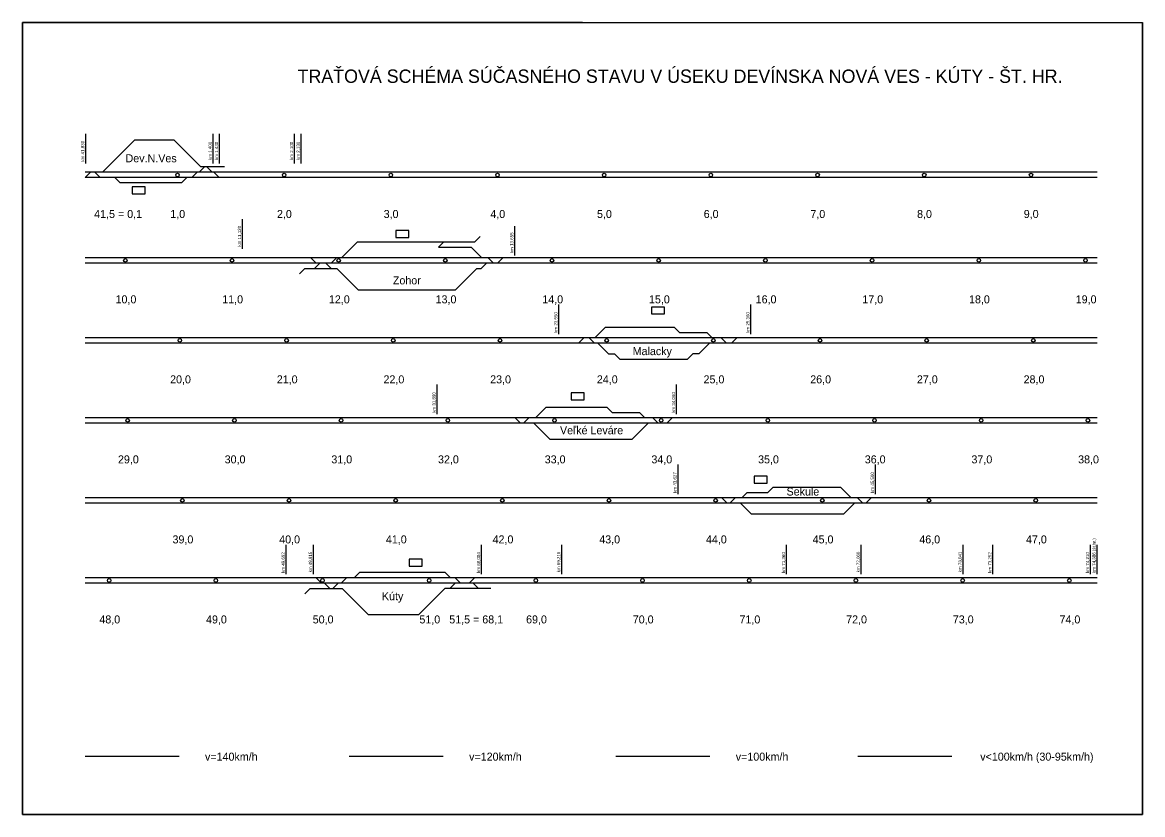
# Model space of a CAD drawing. Extents: x 44 to 1904, y 374 to 671.
# Drawn here: x 44.1 to 464.1, y 373.6 to 670.6 of the extents above; entities that cross this region are included whole.
import ezdxf

# ---------------------------------------------------------------- set-up
doc = ezdxf.new("R2010")
doc.units = 0
for name, color, linetype in [('2', 7, 'Continuous'), ('NAVRH', 7, 'Continuous'), ('Vrstva 1', 7, 'Continuous')]:
    doc.layers.add(name, color=color, linetype=linetype)

msp = doc.modelspace()

# ---------------------------------------------------------------- linework, layer by layer
at = {"layer": '2'}
for p, q in [((297.69, 546.39), (295.39, 546.39)), ((173.74, 448.65), (192.74, 448.65))]:
    msp.add_line(p, q, dxfattribs=at)
at = {"layer": 'NAVRH'}
for p, q in [((74.13, 614.39), (86.13, 626.39)), ((110.92, 616.39), (100.92, 626.39)), ((67.56, 612.39), (69.56, 614.39)), ((73.19, 612.39), (71.19, 614.39)), ((107.55, 612.39), (109.55, 614.39)), ((110.29, 614.39), (112.29, 616.39)), ((115.24, 614.39), (113.24, 616.39)), ((117.85, 612.39), (115.85, 614.39)), ((80.67, 610.39), (78.67, 612.39)), ((103.74, 610.39), (105.74, 612.39)), ((163.68, 582.39), (169.68, 588.39)), ((200.09, 586.39), (202.09, 588.39)), ((213.68, 588.39), (215.68, 590.39)), ((216.37, 582.39), (212.37, 586.39)), ((154.27, 580.39), (152.27, 582.39)), ((153.63, 578.39), (155.63, 580.39)), ((159.81, 578.39), (157.81, 580.39)), ((159.83, 580.39), (161.83, 582.39)), ((216.04, 578.39), (218.04, 580.39)), ((220.73, 580.39), (218.73, 582.39)), ((222.25, 580.39), (224.25, 582.39)), ((147.91, 576.39), (149.91, 578.39)), ((170.01, 570.39), (162.01, 578.39)), ((206.52, 570.39), (214.52, 578.39)), ((258.7, 552.39), (262.7, 556.39)), ((288.49, 556.39), (290.49, 554.39)), ((252.63, 550.39), (254.63, 552.39)), ((258.59, 550.39), (256.59, 552.39)), ((259.86, 550.39), (263.86, 546.39)), ((297.69, 546.39), (301.69, 550.39)), ((300.67, 554.39), (302.67, 552.39)), ((308.07, 550.39), (306.07, 552.39)), ((309.9, 550.39), (311.9, 552.39)), ((266.02, 546.39), (268.02, 544.39)), ((293.39, 544.39), (295.39, 546.39)), ((236.44, 522.39), (240.44, 526.39)), ((265.24, 524.39), (263.24, 526.39)), ((230.86, 520.39), (228.86, 522.39)), ((231.92, 520.39), (233.92, 522.39)), ((277.41, 522.39), (275.41, 524.39)), ((282.47, 520.39), (280.47, 522.39)), ((285.73, 520.39), (287.73, 522.39)), ((241.87, 514.39), (235.87, 520.39)), ((272.7, 514.39), (278.7, 520.39)), ((323.51, 494.39), (325.51, 496.39)), ((354.84, 492.39), (350.84, 496.39)), ((308.29, 490.39), (306.29, 492.39)), ((309.34, 490.39), (311.34, 492.39)), ((313.87, 492.39), (315.87, 494.39)), ((359.23, 490.39), (357.23, 492.39)), ((360.29, 490.39), (362.29, 492.39)), ((317.3, 486.39), (313.3, 490.39)), ((352.12, 486.39), (356.12, 490.39)), ((156.27, 460.39), (154.27, 462.39)), ((163.6, 460.39), (165.6, 462.39)), ((170.52, 464.39), (168.52, 462.39)), ((202.62, 464.39), (204.62, 462.39)), ((208.34, 460.39), (206.34, 462.39)), ((211.59, 460.39), (213.59, 462.39)), ((149.91, 456.39), (151.91, 458.39)), ((159.33, 458.39), (157.33, 460.39)), ((160.45, 458.39), (162.45, 460.39)), ((173.74, 448.65), (164.01, 458.39)), ((192.74, 448.65), (202.47, 458.39)), ((204.3, 458.39), (206.3, 460.39)), ((215.12, 458.39), (213.12, 460.39))]:
    msp.add_line(p, q, dxfattribs=at)
for points in [[(85.27, 606.36), (90.16, 606.36), (90.16, 608.96), (85.27, 608.96)], [(184.07, 589.93), (188.97, 589.93), (188.97, 592.54), (184.07, 592.54)], [(279.94, 561.29), (284.84, 561.29), (284.84, 563.89), (279.94, 563.89)], [(249.79, 529.1), (254.68, 529.1), (254.68, 531.7), (249.79, 531.7)], [(318.48, 497.85), (323.37, 497.85), (323.37, 500.45), (318.48, 500.45)], [(189.1, 466.7), (193.99, 466.7), (193.99, 469.3), (189.1, 469.3)]]:
    msp.add_lwpolyline(points, close=True, dxfattribs=at)
for centre in [(102.21, 613.39), (142.21, 613.39), (182.21, 613.39), (222.21, 613.39), (262.21, 613.39), (302.21, 613.39), (342.21, 613.39), (382.21, 613.39), (422.21, 613.39), (82.66, 581.39), (122.66, 581.39), (162.66, 581.39), (202.66, 581.39), (242.66, 581.39), (282.66, 581.39), (322.66, 581.39), (362.66, 581.39), (402.66, 581.39), (442.66, 581.39), (103.12, 551.39), (143.12, 551.39), (183.12, 551.39), (223.12, 551.39), (263.12, 551.39), (303.12, 551.39), (343.12, 551.39), (383.12, 551.39), (423.12, 551.39), (83.57, 521.39), (123.57, 521.39), (163.57, 521.39), (203.57, 521.39), (243.57, 521.39), (283.57, 521.39), (323.57, 521.39), (363.57, 521.39), (403.57, 521.39), (443.57, 521.39), (104.02, 491.39), (144.02, 491.39), (184.02, 491.39), (224.02, 491.39), (264.02, 491.39), (304.02, 491.39), (344.02, 491.39), (384.02, 491.39), (424.02, 491.39), (76.59, 461.39), (76.59, 461.39), (116.59, 461.39), (156.59, 461.39), (196.59, 461.39), (236.59, 461.39), (276.59, 461.39), (316.59, 461.39), (356.59, 461.39), (396.59, 461.39), (436.59, 461.39)]:
    msp.add_circle(centre, 0.666, dxfattribs=at)
at = {"layer": 'Vrstva 1'}
for p, q in [((254.08, 670.6), (44.08, 670.6)), ((44.08, 670.6), (44.08, 373.6)), ((254.08, 670.6), (464.08, 670.6)), ((464.08, 373.6), (464.08, 670.6)), ((67.82, 617.71), (67.82, 628.79)), ((100.92, 626.39), (86.13, 626.39)), ((115.59, 617.71), (115.59, 628.79)), ((118.03, 617.71), (118.03, 628.79)), ((146.15, 617.71), (146.15, 628.79)), ((148.58, 617.71), (148.58, 628.79)), ((115.85, 614.39), (67.56, 614.39)), ((119.82, 616.39), (110.92, 616.39)), ((146.21, 614.39), (115.85, 614.39)), ((373.08, 614.39), (146.21, 614.39)), ((447.1, 614.39), (373.08, 614.39)), ((117.85, 612.39), (67.56, 612.39)), ((103.74, 610.39), (80.67, 610.39)), ((148.37, 612.39), (117.85, 612.39)), ((373.08, 612.39), (148.37, 612.39)), ((447.1, 612.39), (373.08, 612.39)), ((126.6, 585.71), (126.6, 596.79)), ((228.7, 583.16), (228.7, 594.24)), ((169.68, 588.39), (213.68, 588.39)), ((200.09, 586.39), (212.37, 586.39)), ((126.66, 582.39), (67.56, 582.39)), ((126.66, 580.39), (67.56, 580.39)), ((211.4, 582.39), (126.66, 582.39)), ((228.66, 580.39), (126.66, 580.39)), ((393.54, 582.39), (211.4, 582.39)), ((393.54, 580.39), (228.66, 580.39)), ((447.1, 582.39), (393.54, 582.39)), ((447.1, 580.39), (393.54, 580.39)), ((149.91, 578.39), (162.01, 578.39)), ((214.52, 578.39), (216.04, 578.39)), ((170.01, 570.39), (206.52, 570.39)), ((245.23, 553.71), (245.23, 564.79)), ((317.23, 553.71), (317.23, 564.79)), ((262.7, 556.39), (288.49, 556.39)), ((252.07, 552.39), (67.56, 552.39)), ((245.12, 550.39), (67.56, 550.39)), ((317.12, 550.39), (245.12, 550.39)), ((317.12, 552.39), (252.08, 552.39)), ((290.49, 554.39), (300.67, 554.39)), ((393.54, 552.39), (317.12, 552.39)), ((393.54, 550.39), (317.12, 550.39)), ((447.1, 552.39), (393.54, 552.39)), ((447.1, 550.39), (393.54, 550.39)), ((263.86, 546.39), (266.02, 546.39)), ((268.02, 544.39), (293.39, 544.39)), ((199.57, 523.71), (199.57, 534.79)), ((289.35, 523.71), (289.35, 534.79)), ((240.44, 526.39), (263.24, 526.39)), ((199.57, 522.39), (67.56, 522.39)), ((229.66, 522.39), (199.57, 522.39)), ((434.45, 522.39), (229.66, 522.39)), ((265.24, 524.39), (275.41, 524.39)), ((447.1, 522.39), (434.45, 522.39)), ((199.57, 520.39), (67.56, 520.39)), ((289.48, 520.39), (199.57, 520.39)), ((434.45, 520.39), (289.48, 520.39)), ((447.1, 520.39), (434.45, 520.39)), ((241.87, 514.39), (272.7, 514.39)), ((289.9, 493.71), (289.9, 504.79)), ((363.9, 493.71), (363.9, 504.79)), ((325.51, 496.39), (350.84, 496.39)), ((290.02, 492.39), (67.56, 492.39)), ((364.02, 492.39), (290.02, 492.39)), ((315.87, 494.39), (323.51, 494.39)), ((447.1, 492.39), (364.02, 492.39)), ((290.02, 490.39), (67.56, 490.39)), ((364.02, 490.39), (290.02, 490.39)), ((447.1, 490.39), (364.02, 490.39)), ((317.3, 486.39), (352.12, 486.39)), ((142.98, 463.71), (142.98, 474.79)), ((153.2, 463.71), (153.2, 474.79)), ((216.25, 463.71), (216.25, 474.79)), ((246.27, 463.71), (246.27, 474.79)), ((330.59, 463.71), (330.59, 474.79)), ((358.59, 463.71), (358.59, 474.79)), ((396.78, 463.71), (396.78, 474.79)), ((407.92, 463.71), (407.92, 474.79)), ((444.59, 463.71), (444.59, 474.79)), ((447.02, 463.71), (447.02, 474.79)), ((142.98, 462.39), (67.56, 462.39)), ((153.2, 462.39), (142.98, 462.39)), ((216.25, 462.39), (153.2, 462.39)), ((202.62, 464.39), (170.52, 464.39)), ((246.27, 462.39), (216.25, 462.39)), ((330.59, 462.39), (246.27, 462.39)), ((358.59, 462.39), (330.59, 462.39)), ((396.78, 462.39), (358.59, 462.39)), ((407.92, 462.39), (396.78, 462.39)), ((444.59, 462.39), (407.92, 462.39)), ((447.02, 462.39), (444.59, 462.39)), ((142.98, 460.39), (67.56, 460.39)), ((153.2, 460.39), (142.98, 460.39)), ((151.91, 458.39), (164.01, 458.39)), ((216.25, 460.39), (153.2, 460.39)), ((219.71, 458.39), (202.47, 458.39)), ((246.27, 460.39), (216.25, 460.39)), ((330.59, 460.39), (246.27, 460.39)), ((358.59, 460.39), (330.59, 460.39)), ((396.78, 460.39), (358.59, 460.39)), ((407.92, 460.39), (396.78, 460.39)), ((444.59, 460.39), (407.92, 460.39)), ((447.02, 460.39), (444.59, 460.39)), ((102.81, 395.32), (67.56, 395.32)), ((201.82, 395.32), (166.57, 395.32)), ((301.81, 395.32), (266.56, 395.32)), ((392.59, 395.32), (357.34, 395.32)), ((44.08, 373.6), (254.08, 373.6)), ((254.08, 373.6), (464.08, 373.6))]:
    msp.add_line(p, q, dxfattribs=at)
msp.add_lwpolyline([(44.08, 670.6), (464.08, 670.6), (464.08, 373.6), (44.08, 373.6)], close=True, dxfattribs=at)

# ---------------------------------------------------------------- texts
at = {"layer": 'NAVRH'}
for s, height, p in [('TRAŤOVÁ SCHÉMA SÚČASNÉHO STAVU V ÚSEKU DEVÍNSKA NOVÁ VES - KÚTY - ŠT. HR.', 5, (147.24, 647.93)), ('41,5 = 0,1', 3, (70.99, 597.27)), ('3,0', 3, (179.52, 597.27)), ('4,0', 3, (219.52, 597.27)), ('5,0', 3, (259.52, 597.27)), ('6,0', 3, (299.52, 597.27)), ('7,0', 3, (339.52, 597.27)), ('8,0', 3, (379.52, 597.27)), ('9,0', 3, (419.52, 597.27)), ('10,0', 3, (79, 565.27)), ('11,0', 3, (119, 565.27)), ('Malacky', 3, (272.89, 545.86)), ('26,0', 3, (339.46, 535.27)), ('27,0', 3, (379.46, 535.27)), ('28,0', 3, (419.46, 535.27)), ('Veľké Leváre', 3, (245.64, 516.19)), ('29,0', 3, (79.91, 505.27)), ('30,0', 3, (119.91, 505.27)), ('31,0', 3, (159.91, 505.27)), ('Sekule', 3, (330.58, 493.21)), ('Kúty', 3, (178.88, 453.97)), ('51,5 = 68,1', 3, (204.12, 445.27)), ('v=140km/h', 3, (112.54, 393.82)), ('v=120km/h', 3, (211.56, 393.82)), ('v=100km/h', 3, (311.54, 393.82)), ('v<100km/h (30-95km/h)', 3, (403.2, 393.82))]:
    msp.add_text(s, height=height, dxfattribs=at).set_placement(p)
for s, p in [('Dev.N.Ves', (82.75, 618.16)), ('1,0', (99.52, 597.27)), ('2,0', (139.52, 597.27)), ('Zohor', (182.98, 572.38)), ('12,0', (159, 565.27)), ('13,0', (199, 565.27)), ('14,0', (239, 565.27)), ('15,0', (279, 565.27)), ('16,0', (319, 565.27)), ('17,0', (359, 565.27)), ('18,0', (399, 565.27)), ('19,0', (439, 565.27)), ('20,0', (99.46, 535.27)), ('21,0', (139.46, 535.27)), ('22,0', (179.46, 535.27)), ('23,0', (219.46, 535.27)), ('24,0', (259.46, 535.27)), ('25,0', (299.46, 535.27)), ('32,0', (199.91, 505.27)), ('33,0', (239.91, 505.27)), ('34,0', (279.91, 505.27)), ('35,0', (319.91, 505.27)), ('36,0', (359.91, 505.27)), ('37,0', (399.91, 505.27)), ('38,0', (439.91, 505.27)), ('39,0', (100.36, 475.27)), ('40,0', (140.36, 475.27)), ('41,0', (180.36, 475.27)), ('42,0', (220.36, 475.27)), ('43,0', (260.36, 475.27)), ('44,0', (300.36, 475.27)), ('45,0', (340.36, 475.27)), ('46,0', (380.36, 475.27)), ('47,0', (420.36, 475.27)), ('48,0', (72.93, 445.27)), ('49,0', (112.93, 445.27)), ('50,0', (152.93, 445.27)), ('51,0', (192.93, 445.27)), ('69,0', (232.93, 445.27)), ('70,0', (272.93, 445.27)), ('71,0', (312.93, 445.27)), ('72,0', (352.93, 445.27)), ('73,0', (392.93, 445.27)), ('74,0', (432.93, 445.27))]:
    msp.add_text(s, height=3, rotation=360, dxfattribs=at).set_placement(p)
at = {"layer": 'Vrstva 1'}
for s, p in [('km 41,830', (67.26, 618.44)), ('km 1,400', (115.04, 619.04)), ('km 1,430', (117.47, 619.04)), ('km 2,100', (145.59, 619.04)), ('km 2,130', (148.03, 619.04)), ('km 11,120', (126.05, 586.57)), ('km 13,655', (228.15, 584.11)), ('km 23,550', (244.68, 554.24)), ('km 25,360', (316.68, 554.24)), ('km 31,890', (199.01, 524.24)), ('km 34,060', (288.8, 524.24)), ('km 43,627', (289.34, 494.24)), ('km 45,500', (363.34, 494.24)), ('km 74,386 (št.hr.)', (446.46, 464.19)), ('km 49,692', (142.43, 464.23)), ('km 49,915', (152.65, 464.42)), ('km 68,084', (215.7, 464.23)), ('km 69,215', (245.71, 464.44)), ('km 71,360', (330.04, 464.23)), ('km 72,060', (358.04, 464.44)), ('km 73,041', (396.23, 464.44)), ('km 73,252', (407.37, 464.24)), ('km 74,210', (444.04, 464.23))]:
    msp.add_text(s, height=1.2, rotation=90, dxfattribs=at).set_placement(p)

doc.saveas('drawing.dxf')
